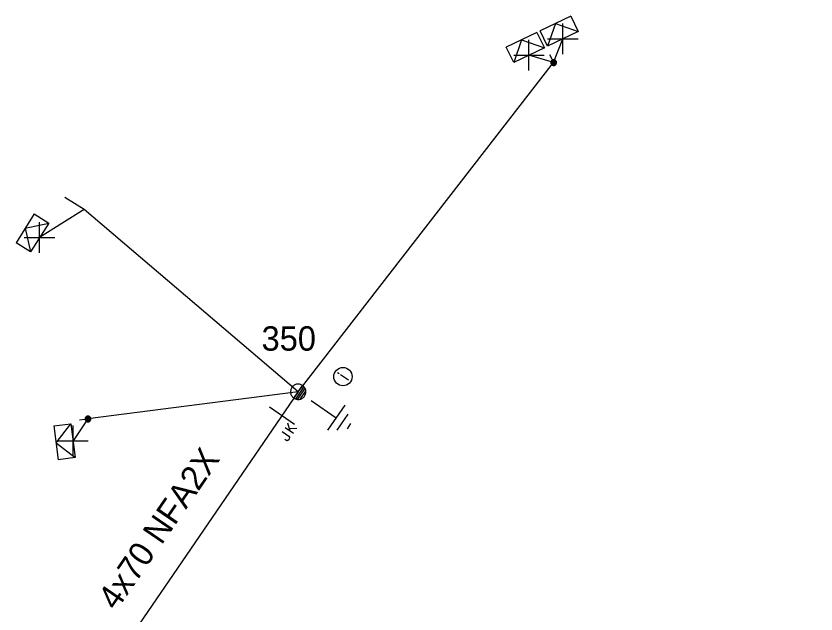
# Model space of a CAD drawing. Extents: x -540466 to -537383, y -1184038 to -1179972.
# Drawn here: x -538086.73 to -538053.92, y -1180815.2 to -1180790.66 of the extents above; entities that cross this region are included whole.
import ezdxf

# ---------------------------------------------------------------- set-up
doc = ezdxf.new("R2010")
doc.units = 0
for name, color, linetype in [('Vrstva 1', 7, 'Continuous'), ('Vrstva 10', 7, 'Continuous'), ('Vrstva 13', 7, 'Continuous'), ('Vrstva 14', 7, 'Continuous'), ('Vrstva 15', 7, 'Continuous'), ('Vrstva 18', 7, 'Continuous'), ('Vrstva 2', 7, 'Continuous'), ('Vrstva 31', 7, 'Continuous'), ('Vrstva 34', 7, 'Continuous'), ('Vrstva 36', 7, 'Continuous'), ('Vrstva 50', 7, 'Continuous'), ('Vrstva 51', 7, 'Continuous'), ('Vrstva 59', 7, 'Continuous'), ('Vrstva 8', 7, 'Continuous'), ('Vrstva 9', 7, 'Continuous')]:
    doc.layers.add(name, color=color, linetype=linetype)

# ---------------------------------------------------------------- blocks, each defined once
blk = doc.blocks.new('NN440')
at = {"layer": 'Vrstva 2'}
for points in [[(0.631, -0.004), (0.627, 0.062), (0.617, 0.127), (0.6, 0.191), (0.577, 0.252), (0.547, 0.311), (0.511, 0.366), (0.469, 0.417), (0.423, 0.464), (0.371, 0.505), (0.316, 0.542), (0.257, 0.571), (0.196, 0.595), (0.132, 0.612), (0.067, 0.622), (0.001, 0.626), (-0.065, 0.622), (-0.13, 0.612), (-0.194, 0.595), (-0.255, 0.571), (-0.314, 0.542), (-0.369, 0.505), (-0.42, 0.464), (-0.467, 0.417), (-0.509, 0.366), (-0.544, 0.311), (-0.574, 0.252), (-0.598, 0.191), (-0.615, 0.127), (-0.626, 0.062), (-0.629, -0.004), (-0.626, -0.07), (-0.615, -0.135), (-0.598, -0.199), (-0.574, -0.26), (-0.544, -0.319), (-0.509, -0.374), (-0.467, -0.426), (-0.42, -0.472), (-0.369, -0.514), (-0.314, -0.55), (-0.255, -0.58), (-0.194, -0.603), (-0.13, -0.62), (-0.065, -0.631), (0.001, -0.634), (0.067, -0.631), (0.132, -0.62), (0.196, -0.603), (0.257, -0.58), (0.316, -0.55), (0.371, -0.514), (0.423, -0.472), (0.469, -0.426), (0.511, -0.374), (0.547, -0.319), (0.577, -0.26), (0.6, -0.199), (0.617, -0.135), (0.627, -0.07), (0.631, -0.004)], [(-0.631, 0), (0.629, 0)], [(-0.601, -0.177), (0.57, -0.177)], [(-0.513, -0.325), (0.501, -0.325)], [(-0.375, -0.473), (0.353, -0.473)]]:
    blk.add_lwpolyline(points, dxfattribs=at)
blk = doc.blocks.new('NN840')
at = {"layer": 'Vrstva 15'}
for points in [[(0.003, 0.619), (0.003, -0.631)], [(-0.538, -0.385), (-0.538, -0.71)], [(-0.332, -0.385), (-0.332, -0.798)], [(-0.332, -0.641), (-0.125, -0.385)], [(-0.263, -0.557), (-0.091, -0.798)], [(-0.745, -0.71), (-0.745, -0.66)], [(-0.73, -0.764), (-0.745, -0.71)], [(-0.657, -0.798), (-0.73, -0.764)], [(-0.627, -0.798), (-0.657, -0.798)], [(-0.558, -0.764), (-0.627, -0.798)], [(-0.538, -0.71), (-0.558, -0.764)]]:
    blk.add_lwpolyline(points, dxfattribs=at)
blk = doc.blocks.new('NN770')
at = {"layer": 'Vrstva 10'}
for p, q in [((0.002, 0.187), (0.002, 0.263)), ((0.002, -0.276), (0.002, 0.111))]:
    blk.add_line(p, q, dxfattribs=at)
blk.add_circle((0, -0.008), 0.375, dxfattribs=at)
blk = doc.blocks.new('NN800')
at = {"layer": 'Vrstva 1'}
for points in [[(-0.442, 0.442), (0.442, -0.442)], [(-0.442, -0.442), (0.442, 0.442)]]:
    blk.add_lwpolyline(points, dxfattribs=at)
blk = doc.blocks.new('NN630')
at = {"layer": 'Vrstva 9'}
for points in [[(-0.003, -0.7), (-0.703, 0)], [(-0.703, -0.7), (-0.703, 0), (0.697, 0), (0.697, -0.7)], [(-0.003, -0.7), (0.697, 0)], [(-0.703, -0.7), (0.697, -0.7)]]:
    blk.add_lwpolyline(points, dxfattribs=at)
blk = doc.blocks.new('NN810')
at = {"layer": 'Vrstva 14'}
for points in [[(0.004, -0.64), (0.004, -1.89)], [(0.629, -1.89), (-0.621, -1.89)], [(0.388, -2.2), (-0.399, -2.2)], [(0.004, -2.515), (-0.124, -2.515)], [(0.137, -2.515), (0.004, -2.515)]]:
    blk.add_lwpolyline(points, dxfattribs=at)
blk = doc.blocks.new('NN500')
at = {"layer": 'Vrstva 2'}
for points in [[(-0.001, -0.235), (0.023, -0.234), (0.048, -0.23), (0.071, -0.224), (0.094, -0.215), (0.116, -0.204), (0.137, -0.191), (0.156, -0.175), (0.173, -0.158), (0.189, -0.139), (0.202, -0.118), (0.213, -0.096), (0.222, -0.073), (0.229, -0.049), (0.232, -0.025), (0.234, 0), (0.232, 0.024), (0.229, 0.048), (0.222, 0.072), (0.213, 0.095), (0.202, 0.117), (0.189, 0.138), (0.173, 0.157), (0.156, 0.174), (0.137, 0.19), (0.116, 0.203), (0.094, 0.214), (0.071, 0.223), (0.048, 0.229), (0.023, 0.233), (-0.001, 0.235), (-0.026, 0.233), (-0.05, 0.229), (-0.074, 0.223), (-0.097, 0.214), (-0.119, 0.203), (-0.139, 0.19), (-0.158, 0.174), (-0.176, 0.157), (-0.191, 0.138), (-0.205, 0.117), (-0.216, 0.095), (-0.225, 0.072), (-0.231, 0.048), (-0.235, 0.024), (-0.236, 0), (-0.235, -0.025), (-0.231, -0.049), (-0.225, -0.073), (-0.216, -0.096), (-0.205, -0.118), (-0.191, -0.139), (-0.176, -0.158), (-0.158, -0.175), (-0.139, -0.191), (-0.119, -0.204), (-0.097, -0.215), (-0.074, -0.224), (-0.05, -0.23), (-0.026, -0.234), (-0.001, -0.235)], [(-0.001, -0.235), (0.023, -0.234), (0.048, -0.23), (0.071, -0.224), (0.094, -0.215), (0.116, -0.204), (0.137, -0.191), (0.156, -0.175), (0.173, -0.158), (0.189, -0.139), (0.202, -0.118), (0.213, -0.096), (0.222, -0.073), (0.229, -0.049), (0.232, -0.025), (0.234, 0), (0.232, 0.024), (0.229, 0.048), (0.222, 0.072), (0.213, 0.095), (0.202, 0.117), (0.189, 0.138), (0.173, 0.157), (0.156, 0.174), (0.137, 0.19), (0.116, 0.203), (0.094, 0.214), (0.071, 0.223), (0.048, 0.229), (0.023, 0.233), (-0.001, 0.235), (-0.026, 0.233), (-0.05, 0.229), (-0.074, 0.223), (-0.097, 0.214), (-0.119, 0.203), (-0.139, 0.19), (-0.158, 0.174), (-0.176, 0.157), (-0.191, 0.138), (-0.205, 0.117), (-0.216, 0.095), (-0.225, 0.072), (-0.231, 0.048), (-0.235, 0.024), (-0.236, 0), (-0.235, -0.025), (-0.231, -0.049), (-0.225, -0.073), (-0.216, -0.096), (-0.205, -0.118), (-0.191, -0.139), (-0.176, -0.158), (-0.158, -0.175), (-0.139, -0.191), (-0.119, -0.204), (-0.097, -0.215), (-0.074, -0.224), (-0.05, -0.23), (-0.026, -0.234), (-0.001, -0.235)], [(-0.001, -0.206), (0.02, -0.205), (0.041, -0.201), (0.062, -0.196), (0.082, -0.188), (0.101, -0.178), (0.12, -0.167), (0.136, -0.153), (0.151, -0.138), (0.165, -0.121), (0.177, -0.103), (0.186, -0.084), (0.194, -0.064), (0.2, -0.043), (0.203, -0.022), (0.204, 0), (0.203, 0.021), (0.2, 0.042), (0.194, 0.063), (0.186, 0.083), (0.177, 0.102), (0.165, 0.12), (0.151, 0.137), (0.136, 0.152), (0.12, 0.166), (0.101, 0.177), (0.082, 0.187), (0.062, 0.195), (0.041, 0.2), (0.02, 0.204), (-0.001, 0.205), (-0.023, 0.204), (-0.044, 0.2), (-0.065, 0.195), (-0.085, 0.187), (-0.104, 0.177), (-0.122, 0.166), (-0.139, 0.152), (-0.154, 0.137), (-0.167, 0.12), (-0.179, 0.102), (-0.189, 0.083), (-0.197, 0.063), (-0.202, 0.042), (-0.205, 0.021), (-0.207, 0), (-0.205, -0.022), (-0.202, -0.043), (-0.197, -0.064), (-0.189, -0.084), (-0.179, -0.103), (-0.167, -0.121), (-0.154, -0.138), (-0.139, -0.153), (-0.122, -0.167), (-0.104, -0.178), (-0.085, -0.188), (-0.065, -0.196), (-0.044, -0.201), (-0.023, -0.205), (-0.001, -0.206)], [(-0.001, -0.176), (0.017, -0.175), (0.035, -0.172), (0.053, -0.168), (0.07, -0.161), (0.087, -0.153), (0.102, -0.143), (0.116, -0.131), (0.129, -0.118), (0.141, -0.104), (0.151, -0.088), (0.159, -0.072), (0.166, -0.055), (0.171, -0.037), (0.174, -0.019), (0.175, 0), (0.174, 0.018), (0.171, 0.036), (0.166, 0.054), (0.159, 0.071), (0.151, 0.087), (0.141, 0.103), (0.129, 0.117), (0.116, 0.13), (0.102, 0.142), (0.087, 0.152), (0.07, 0.16), (0.053, 0.167), (0.035, 0.172), (0.017, 0.174), (-0.001, 0.175), (-0.02, 0.174), (-0.038, 0.172), (-0.056, 0.167), (-0.073, 0.16), (-0.089, 0.152), (-0.105, 0.142), (-0.119, 0.13), (-0.132, 0.117), (-0.143, 0.103), (-0.153, 0.087), (-0.162, 0.071), (-0.168, 0.054), (-0.173, 0.036), (-0.176, 0.018), (-0.177, 0), (-0.176, -0.019), (-0.173, -0.037), (-0.168, -0.055), (-0.162, -0.072), (-0.153, -0.088), (-0.143, -0.104), (-0.132, -0.118), (-0.119, -0.131), (-0.105, -0.143), (-0.089, -0.153), (-0.073, -0.161), (-0.056, -0.168), (-0.038, -0.172), (-0.02, -0.175), (-0.001, -0.176)], [(-0.001, -0.147), (0.014, -0.146), (0.029, -0.143), (0.044, -0.139), (0.058, -0.134), (0.072, -0.127), (0.085, -0.119), (0.097, -0.109), (0.107, -0.098), (0.117, -0.086), (0.125, -0.073), (0.132, -0.06), (0.138, -0.046), (0.142, -0.031), (0.144, -0.016), (0.145, 0), (0.144, 0.015), (0.142, 0.03), (0.138, 0.045), (0.132, 0.059), (0.125, 0.073), (0.117, 0.086), (0.107, 0.097), (0.097, 0.108), (0.085, 0.118), (0.072, 0.126), (0.058, 0.133), (0.044, 0.139), (0.029, 0.143), (0.014, 0.145), (-0.001, 0.146), (-0.017, 0.145), (-0.032, 0.143), (-0.046, 0.139), (-0.061, 0.133), (-0.074, 0.126), (-0.087, 0.118), (-0.099, 0.108), (-0.11, 0.097), (-0.119, 0.086), (-0.128, 0.073), (-0.135, 0.059), (-0.14, 0.045), (-0.144, 0.03), (-0.147, 0.015), (-0.147, 0), (-0.147, -0.016), (-0.144, -0.031), (-0.14, -0.046), (-0.135, -0.06), (-0.128, -0.073), (-0.119, -0.086), (-0.11, -0.098), (-0.099, -0.109), (-0.087, -0.119), (-0.074, -0.127), (-0.061, -0.134), (-0.046, -0.139), (-0.032, -0.143), (-0.017, -0.146), (-0.001, -0.147)], [(-0.001, -0.117), (0.011, -0.116), (0.023, -0.114), (0.035, -0.111), (0.046, -0.107), (0.057, -0.101), (0.067, -0.095), (0.077, -0.087), (0.085, -0.078), (0.093, -0.069), (0.1, -0.059), (0.105, -0.048), (0.11, -0.036), (0.113, -0.025), (0.115, -0.013), (0.115, 0), (0.115, 0.012), (0.113, 0.024), (0.11, 0.036), (0.105, 0.047), (0.1, 0.058), (0.093, 0.068), (0.085, 0.078), (0.077, 0.086), (0.067, 0.094), (0.057, 0.101), (0.046, 0.106), (0.035, 0.11), (0.023, 0.114), (0.011, 0.116), (-0.001, 0.116), (-0.013, 0.116), (-0.025, 0.114), (-0.037, 0.11), (-0.049, 0.106), (-0.059, 0.101), (-0.07, 0.094), (-0.079, 0.086), (-0.088, 0.078), (-0.096, 0.068), (-0.102, 0.058), (-0.108, 0.047), (-0.112, 0.036), (-0.115, 0.024), (-0.117, 0.012), (-0.118, 0), (-0.117, -0.013), (-0.115, -0.025), (-0.112, -0.036), (-0.108, -0.048), (-0.102, -0.059), (-0.096, -0.069), (-0.088, -0.078), (-0.079, -0.087), (-0.07, -0.095), (-0.059, -0.101), (-0.049, -0.107), (-0.037, -0.111), (-0.025, -0.114), (-0.013, -0.116), (-0.001, -0.117)], [(-0.001, -0.087), (0.008, -0.087), (0.017, -0.085), (0.026, -0.083), (0.034, -0.08), (0.042, -0.076), (0.05, -0.071), (0.057, -0.065), (0.063, -0.059), (0.069, -0.051), (0.074, -0.044), (0.078, -0.036), (0.081, -0.027), (0.084, -0.019), (0.085, -0.01), (0.086, 0), (0.085, 0.009), (0.084, 0.018), (0.081, 0.026), (0.078, 0.035), (0.074, 0.043), (0.069, 0.051), (0.063, 0.058), (0.057, 0.064), (0.05, 0.07), (0.042, 0.075), (0.034, 0.079), (0.026, 0.082), (0.017, 0.085), (0.008, 0.086), (-0.001, 0.087), (-0.01, 0.086), (-0.019, 0.085), (-0.028, 0.082), (-0.037, 0.079), (-0.045, 0.075), (-0.052, 0.07), (-0.059, 0.064), (-0.066, 0.058), (-0.072, 0.051), (-0.077, 0.043), (-0.081, 0.035), (-0.084, 0.026), (-0.086, 0.018), (-0.088, 0.009), (-0.088, 0), (-0.088, -0.01), (-0.086, -0.019), (-0.084, -0.027), (-0.081, -0.036), (-0.077, -0.044), (-0.072, -0.052), (-0.066, -0.059), (-0.059, -0.065), (-0.052, -0.071), (-0.045, -0.076), (-0.037, -0.08), (-0.028, -0.083), (-0.019, -0.085), (-0.01, -0.087), (-0.001, -0.087)], [(-0.001, -0.058), (0.005, -0.057), (0.011, -0.056), (0.016, -0.055), (0.022, -0.053), (0.027, -0.05), (0.032, -0.047), (0.037, -0.043), (0.041, -0.039), (0.045, -0.034), (0.048, -0.029), (0.051, -0.024), (0.053, -0.018), (0.055, -0.012), (0.056, -0.006), (0.056, 0), (0.056, 0.006), (0.055, 0.011), (0.053, 0.017), (0.051, 0.023), (0.048, 0.028), (0.045, 0.033), (0.041, 0.038), (0.037, 0.042), (0.032, 0.046), (0.027, 0.049), (0.022, 0.052), (0.016, 0.054), (0.011, 0.056), (0.005, 0.057), (-0.001, 0.057), (-0.007, 0.057), (-0.013, 0.056), (-0.019, 0.054), (-0.025, 0.052), (-0.03, 0.049), (-0.035, 0.046), (-0.04, 0.042), (-0.044, 0.038), (-0.048, 0.033), (-0.051, 0.028), (-0.054, 0.023), (-0.056, 0.017), (-0.057, 0.011), (-0.058, 0.006), (-0.059, 0), (-0.058, -0.006), (-0.057, -0.012), (-0.056, -0.018), (-0.054, -0.024), (-0.051, -0.029), (-0.048, -0.034), (-0.044, -0.039), (-0.04, -0.043), (-0.035, -0.047), (-0.03, -0.05), (-0.025, -0.053), (-0.019, -0.055), (-0.013, -0.056), (-0.007, -0.057), (-0.001, -0.058)], [(-0.001, -0.028), (0.002, -0.028), (0.005, -0.028), (0.007, -0.027), (0.01, -0.026), (0.013, -0.024), (0.015, -0.023), (0.017, -0.021), (0.019, -0.019), (0.021, -0.017), (0.023, -0.014), (0.024, -0.012), (0.025, -0.009), (0.026, -0.006), (0.026, -0.003), (0.027, 0), (0.026, 0.002), (0.026, 0.005), (0.025, 0.008), (0.024, 0.011), (0.023, 0.013), (0.021, 0.016), (0.019, 0.018), (0.017, 0.02), (0.015, 0.022), (0.013, 0.024), (0.01, 0.025), (0.007, 0.026), (0.005, 0.027), (0.002, 0.027), (-0.001, 0.027), (-0.004, 0.027), (-0.007, 0.027), (-0.01, 0.026), (-0.012, 0.025), (-0.015, 0.024), (-0.018, 0.022), (-0.02, 0.02), (-0.022, 0.018), (-0.024, 0.016), (-0.025, 0.013), (-0.027, 0.011), (-0.028, 0.008), (-0.028, 0.005), (-0.029, 0.002), (-0.029, 0), (-0.029, -0.003), (-0.028, -0.006), (-0.028, -0.009), (-0.027, -0.012), (-0.025, -0.014), (-0.024, -0.017), (-0.022, -0.019), (-0.02, -0.021), (-0.018, -0.023), (-0.015, -0.024), (-0.012, -0.026), (-0.01, -0.027), (-0.007, -0.028), (-0.004, -0.028), (-0.001, -0.028)], [(0.234, 0), (0.704, 0)]]:
    blk.add_lwpolyline(points, dxfattribs=at)
blk = doc.blocks.new('NN510')
at = {"layer": 'Vrstva 2'}
blk.add_lwpolyline([(0.001, 0.002), (0.001, 0.939)], dxfattribs=at)

msp = doc.modelspace()

# ---------------------------------------------------------------- linework, layer by layer
at = {"layer": 'Vrstva 50'}
msp.add_lwpolyline([(-538075.16, -1180806.08), (-538082.578, -1180816.912), (-538075.193, -1180834.507), (-538066.948, -1180834.145), (-538061.578, -1180835.611), (-538046.012, -1180839.963), (-538031.082, -1180834.986)], dxfattribs=at)
at = {"layer": 'Vrstva 59'}
for points in [[(-538064.681, -1180792.573), (-538064.305, -1180791.599)], [(-538064.681, -1180792.573), (-538065.692, -1180792.27)]]:
    msp.add_lwpolyline(points, dxfattribs=at)
at = {"layer": 'Vrstva 8'}
for points in [[(-538075.16, -1180806.08), (-538064.681, -1180792.573)], [(-538075.16, -1180806.08), (-538083.936, -1180798.608), (-538085.77, -1180799.75)], [(-538075.16, -1180806.08), (-538083.785, -1180807.197), (-538084.396, -1180808.09)]]:
    msp.add_lwpolyline(points, dxfattribs=at)

# ---------------------------------------------------------------- block references
at = {"layer": 'Vrstva 13'}
for name, p, xscale, yscale, rotation in [('NN500', (-538064.681, -1180792.573), 0.5000000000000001, 0.5, 115.81400001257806), ('NN440', (-538075.16, -1180806.08), 0.49999999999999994, 0.5000000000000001, 55.59576931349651), ('NN500', (-538083.785, -1180807.197), 0.5, 0.49999999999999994, -172.81399995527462)]:
    msp.add_blockref(name, p, dxfattribs=dict(at, xscale=xscale, yscale=yscale, rotation=rotation))
at = {"layer": 'Vrstva 13', "rotation": 57.567441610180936}
msp.add_blockref('NN510', (-538083.935, -1180798.609), dxfattribs=at)
at = {"layer": 'Vrstva 15', "rotation": 55.59576939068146}
msp.add_blockref('NN810', (-538075.16, -1180806.08), dxfattribs=at)
at = {"layer": 'Vrstva 18', "rotation": 55.59576944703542}
msp.add_blockref('NN840', (-538075.828, -1180807.054), dxfattribs=at)
at = {"layer": 'Vrstva 31'}
for p, rotation in [((-538064.305, -1180791.599), -154.18623337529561), ((-538065.692, -1180792.27), -154.18623349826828), ((-538085.77, -1180799.75), -122.43255831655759), ((-538084.396, -1180808.09), -82.814311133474)]:
    msp.add_blockref('NN630', p, dxfattribs=dict(at, rotation=rotation))
at = {"layer": 'Vrstva 34'}
for p, rotation in [((-538064.305, -1180791.599), 45), ((-538065.692, -1180792.27), 45), ((-538085.77, -1180799.75), 45), ((-538084.396, -1180808.09), 44.99999995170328)]:
    msp.add_blockref('NN800', p, dxfattribs=dict(at, rotation=rotation))
at = {"layer": 'Vrstva 36', "rotation": 55.59576944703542}
msp.add_blockref('NN770', (-538073.331, -1180805.454), dxfattribs=at)

# ---------------------------------------------------------------- texts
at = {"layer": 'Vrstva 14'}
msp.add_text('350', height=1, dxfattribs=at).set_placement((-538076.662, -1180804.394))
at = {"layer": 'Vrstva 51'}
msp.add_text('4x70 NFA2X', height=1, rotation=55.596, dxfattribs=at).set_placement((-538082.619, -1180815.097))

doc.saveas('drawing.dxf')
